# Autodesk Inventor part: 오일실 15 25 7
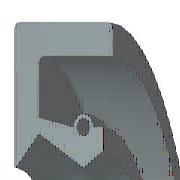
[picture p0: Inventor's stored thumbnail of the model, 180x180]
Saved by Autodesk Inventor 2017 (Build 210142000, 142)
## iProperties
Created: 2012-02
Part Number: 오일실 15 25 7
Material: 고무
Description: 오일-실
Document SubType Name: Modeling
Standard: KS B 2804
Designer: mduedu
Standards Organization: KS
Language: ko-KR
Size Designation: D - 15 25 7
Categories: <MemberInstance><Categories><Category DisplayName="샤프트 부품" InternalName="7f7aeb1f-a693-4053-b835-cee3144e0d98" Mnemonic="SHFT"><Category DisplayName="실링" Intern
Density: 0.93 g/cm^3
Appearance: 고무 - 검은색 - 버전 1.1
IsCustomPart: 1
Author: mduedu
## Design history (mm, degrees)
revolve "본체" stored, may be unused: angle "d17" = 90 deg
revolve "스프링1" stored, may be unused: angle "d18" = 90 deg
body "Solid1"
sketch "스케치1"
  geometry: L1 (0, 12.5)-(7, 12.5); L2 (7, 10.75)-(1.75, 10.75); L3 (1.75, 9.25)-(4.9, 7.5); L4 (4.9, 7.5)-(0, 7.5); L5 (0, 0)-(9.586, 0) reference; L6 (4.9, 7.5)-(6.3, 8.375); L7 (0, 18)-(0, -3) reference; L8 (-1.941, 0)-(11.507, 0) reference; L9 (4.2, 9.6)-(1.75, 10.09); L10 (1.75, 10.09)-(1.75, 10.75); L11 (0, 12.5)-(0, 7.588); L12 (4.9, 7.5)-(0, 7.5); L13 (1.75, 9.25)-(0.152, 7.528); L14 (7, 12.5)-(7, 10.75); L15 (5.6, 9.6)-(6.3, 9.6); L16 (6.3, 9.6)-(6.3, 8.375); C1 r 0.455 at (4.9, 9.6); A1 r 0.7 centre (4.9, 9.6) between (5.6, 9.6) and (4.2, 9.6); A2 r 0.088 centre (0.088, 7.588) between (0, 7.588) and (0.152, 7.528); 1 further point
  constraints: 28 end point, 5 horizontal alignment, 5 point on line, 4 point on circle, 4 vertical alignment, 3 centre point, 3 tangent, 2 collinear, 2 horizontal, 2 perpendicular, 1 coincident, 1 parallel
  dimensions: "d0" = 25 diameter of L1 L5 (= SD2); "d1" = 1.75 distance of L1.end L2.start (= SD); "d2" = 0.91 diameter of C1 (= SPDI); "d3" = 1.4 diameter of A1 (= SPDA); "d4" = 15 diameter of L3.end L5 (= NND); "d5" = 18.5 diameter of L3.start L5 (= TKDM); "d7" = 20.18 diameter of L9.end L5 (= TKDM + 0.24 x SWDT); "d8" = 1.75 distance between parallel lines of L11 L10 (= SD); "d9" = 4.9 distance from line of L11 C1.centre (= SPDST); "d10" = 19.2 diameter of C1.centre L5 (= HLDM); "d11" = 0.0875 radius of A2 (= 0.25 x LAB); "d12" = 6.3 distance between parallel lines of L11 L16 (= SDI); "d13" = 16.75 diameter of L6.end L5 (= ABDM); "d14" = 7 distance from line of L11 L1.end (= SWDT)
fillet "모깎기1" dims "d6" = 0.3 (= RR)
other parameters: "SD2" = 25 [user parameter; used in 1 equation term], "SWDT" = 7 [user parameter; used in 2 equation terms], "RR" = 0.3 [user parameter; used in 1 equation term], "SD" = 1.75 [user parameter; used in 2 equation terms], "NND" = 15 [user parameter; used in 1 equation term], "SPDA" = 1.4 [user parameter; used in 1 equation term], "SPDI" = 0.91 [user parameter; used in 1 equation term], "TKDM" = 18.5 [user parameter; used in 2 equation terms], "HLDM" = 19.2 [user parameter; used in 1 equation term], "ABDM" = 16.75 [user parameter; used in 1 equation term], "SDI" = 6.3 [user parameter; used in 1 equation term], "SPDST" = 4.9 [user parameter; used in 1 equation term], "LAB" = 0.35 [user parameter; used in 1 equation term], "d15" = 0, "d16" = 0, "d19" = 0
